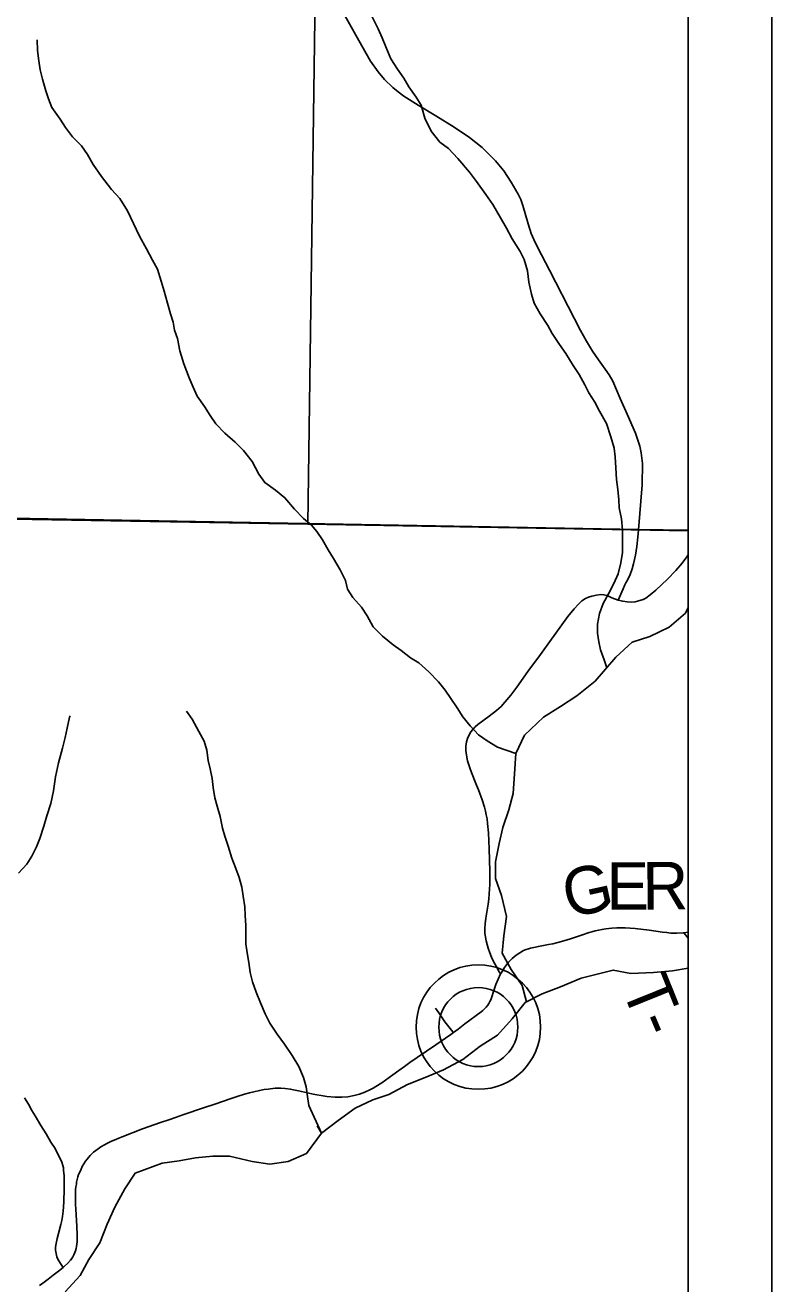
# Model space of a CAD drawing. Extents: x 0 to 34, y -8.9 to 22.
# Drawn here: x 29.724 to 30.617, y 15.866 to 17.37 of the extents above; entities that cross this region are included whole.
import ezdxf

# ---------------------------------------------------------------- set-up
doc = ezdxf.new("R2010")
doc.units = 0
for name, color, linetype in [('GM_X_Corporation', 7, 'Continuous'), ('GM_X_County_Road', 7, 'Continuous'), ('GM_X_County_Road_Text', 7, 'Continuous'), ('GM_X_Minor_River', 7, 'Continuous'), ('GM_X_Township_Road', 7, 'Continuous'), ('GM_X_Township_Road_Text', 7, 'Continuous'), ('GM_X_Unincorporated', 7, 'Continuous'), ('GM_X_Unincorporated_Location', 7, 'Continuous'), ('SH_Data', 7, 'Continuous')]:
    doc.layers.add(name, color=color, linetype=linetype)

msp = doc.modelspace()

# ---------------------------------------------------------------- linework, layer by layer
at = {"layer": 'GM_X_Corporation'}
for points in [[(28.3182, 16.8002), (29.5528, 16.7835), (30.4571, 16.7673), (30.5167, 16.7663), (30.5167, 21.4), (23.7167, 21.4)], [(23.7167, 14.6), (30.5167, 14.6), (30.5167, 16.7663), (30.4571, 16.7673), (29.5528, 16.7835), (28.3182, 16.8002)]]:
    msp.add_lwpolyline(points, dxfattribs=at)
for points in [[(30.5167, 16.7663), (30.5167, 21.4), (28.2203, 21.4), (28.2198, 21.3092), (28.2124, 18.7899), (28.2124, 18.7889), (28.2011, 18.1006), (28.201, 18.0921), (28.1882, 17.3108), (28.1928, 16.8054), (28.3182, 16.8002), (29.5528, 16.7835), (30.4571, 16.7673)], [(30.0751, 17.7225), (30.0622, 16.7735), (29.0733, 16.7902), (29.0677, 17.7366)], [(30.5167, 16.7657), (30.5167, 17.7179), (30.0751, 17.7225), (30.0622, 16.7735)], [(28.1739, 14.6), (30.5167, 14.6), (30.5167, 16.7663), (30.4571, 16.7673), (29.5528, 16.7835), (28.3182, 16.8002), (28.1928, 16.8054), (28.1817, 16.6637), (28.1846, 16.3341), (28.1918, 16.1509), (28.1809, 15.2987)]]:
    msp.add_lwpolyline(points, close=True, dxfattribs=at)
at = {"layer": 'GM_X_County_Road'}
for points in [[(30.4573, 16.7667), (30.4615, 16.8207), (30.4621, 16.8461), (30.4606, 16.8589), (30.4588, 16.8668), (30.4536, 16.8821), (30.4438, 16.9048), (30.4354, 16.9237), (30.4267, 16.9442), (30.4223, 16.9521), (30.4176, 16.9588), (30.4094, 16.97), (30.4025, 16.9801), (30.395, 16.9921), (30.3879, 17.005), (30.3584, 17.0623), (30.3508, 17.077), (30.3414, 17.0954), (30.334, 17.1101), (30.3292, 17.121), (30.3256, 17.1326), (30.3191, 17.1542), (30.3166, 17.1614), (30.3133, 17.1678), (30.3052, 17.1824), (30.2962, 17.1956), (30.2864, 17.2077), (30.2703, 17.2235), (30.2554, 17.2356), (30.237, 17.2478), (30.215, 17.2616), (30.1941, 17.2742), (30.1767, 17.2849), (30.1699, 17.2901), (30.1635, 17.2954), (30.1538, 17.3048), (30.1461, 17.3142), (30.1371, 17.3268), (30.1266, 17.3451), (30.1026, 17.3879)], [(30.433, 16.6827), (30.4334, 16.6836), (30.4373, 16.6926), (30.4388, 16.6963), (30.441, 16.7009), (30.4423, 16.7035), (30.444, 16.7066), (30.4455, 16.7095), (30.4468, 16.712), (30.4482, 16.7156), (30.449, 16.7179), (30.4497, 16.7203), (30.4514, 16.7262), (30.4537, 16.7365), (30.4554, 16.7468), (30.4564, 16.7579), (30.4573, 16.7667)], [(30.433, 16.6827), (30.4384, 16.6813), (30.4438, 16.6805), (30.4493, 16.6804), (30.4535, 16.6808), (30.4588, 16.6821), (30.4628, 16.6835), (30.4659, 16.6852), (30.4714, 16.6891), (30.4781, 16.6946), (30.4921, 16.7077), (30.502, 16.718), (30.5096, 16.7269), (30.5151, 16.7343), (30.5167, 16.7368)], [(30.2925, 16.2361), (30.2908, 16.2385), (30.2875, 16.2444), (30.2836, 16.2517), (30.2817, 16.2561), (30.2797, 16.2611), (30.2778, 16.2668), (30.2764, 16.2713), (30.2753, 16.2756), (30.2744, 16.2798), (30.2737, 16.2852), (30.2736, 16.2903), (30.2739, 16.296), (30.2748, 16.3028), (30.2776, 16.3194), (30.2785, 16.3255), (30.279, 16.3317), (30.2793, 16.3371), (30.2797, 16.3428), (30.2798, 16.3589), (30.279, 16.3855), (30.2781, 16.4048), (30.277, 16.4158), (30.2763, 16.4214), (30.2754, 16.4262), (30.2744, 16.4304), (30.2732, 16.4352), (30.2705, 16.444), (30.2659, 16.4562), (30.2637, 16.4615), (30.2612, 16.4676), (30.2565, 16.4799), (30.2531, 16.4906), (30.2516, 16.4974), (30.2511, 16.503), (30.2511, 16.5081), (30.2518, 16.5132), (30.253, 16.5175), (30.2548, 16.5216), (30.2571, 16.5254), (30.2595, 16.5283), (30.2619, 16.5311), (30.2653, 16.5341), (30.2789, 16.5439), (30.2877, 16.5507), (30.2931, 16.5557), (30.2977, 16.5606), (30.3048, 16.5692), (30.3117, 16.5787), (30.3249, 16.5976), (30.3402, 16.6179), (30.3535, 16.6359), (30.3567, 16.6404), (30.3657, 16.653), (30.373, 16.663), (30.3804, 16.6724), (30.3854, 16.6779), (30.3897, 16.6817), (30.394, 16.6845), (30.3974, 16.6862), (30.4016, 16.6876), (30.4072, 16.6888), (30.4123, 16.6893), (30.4159, 16.6892), (30.4194, 16.6883), (30.4223, 16.6872), (30.4256, 16.6855), (30.433, 16.6827)], [(30.3396, 16.2692), (30.3496, 16.2711), (30.3549, 16.272), (30.3608, 16.2735), (30.3681, 16.2756), (30.376, 16.278), (30.3821, 16.2801), (30.389, 16.2825), (30.3984, 16.2856), (30.4015, 16.2864), (30.4056, 16.2875), (30.4098, 16.2883), (30.4135, 16.2889), (30.4183, 16.2897), (30.4217, 16.2902), (30.4253, 16.2906), (30.4315, 16.291), (30.4366, 16.2912), (30.4415, 16.2911), (30.4534, 16.2903), (30.4701, 16.2883), (30.4861, 16.286), (30.491, 16.2854), (30.4959, 16.2849), (30.5033, 16.2846), (30.5106, 16.285), (30.5115, 16.2852)], [(30.5115, 16.2852), (30.5166, 16.286), (30.5167, 16.286)], [(30.2925, 16.2361), (30.293, 16.2371), (30.297, 16.2435), (30.302, 16.2499), (30.3064, 16.2545), (30.3112, 16.2585), (30.3154, 16.2614), (30.3199, 16.2638), (30.323, 16.2652), (30.3257, 16.2661), (30.3284, 16.2668), (30.3321, 16.2675), (30.3376, 16.2688), (30.3396, 16.2692)], [(30.236, 16.1659), (30.2417, 16.1701), (30.2497, 16.1762), (30.2691, 16.1907), (30.2713, 16.1924), (30.2736, 16.1948), (30.2753, 16.1964), (30.2772, 16.1988), (30.2783, 16.2005), (30.2797, 16.2031), (30.2807, 16.205), (30.2816, 16.2075), (30.2845, 16.2163), (30.2868, 16.2234), (30.2894, 16.2298), (30.2925, 16.2361)], [(29.7695, 15.8851), (29.7709, 15.8862), (29.7754, 15.8902), (29.7786, 15.8939), (29.7802, 15.896), (29.7813, 15.8979), (29.7825, 15.9002), (29.7835, 15.9029), (29.7844, 15.9051), (29.7851, 15.9077), (29.7856, 15.9104), (29.7858, 15.9129), (29.7862, 15.9159), (29.7862, 15.9239), (29.7858, 15.9344), (29.7847, 15.9549), (29.7844, 15.9605), (29.7843, 15.968), (29.7846, 15.978), (29.7849, 15.9814), (29.7854, 15.9849), (29.7856, 15.9871), (29.7862, 15.9903), (29.7871, 15.9935), (29.7881, 15.9961), (29.7894, 15.9992), (29.791, 16.0028), (29.7925, 16.0058), (29.7943, 16.0089), (29.7963, 16.0121), (29.7982, 16.0147), (29.7999, 16.0166), (29.802, 16.019), (29.8038, 16.0208), (29.8061, 16.0229), (29.8086, 16.025), (29.8116, 16.0271), (29.8148, 16.0292), (29.819, 16.0318), (29.8228, 16.0338), (29.8274, 16.036), (29.8325, 16.0382), (29.8361, 16.0398), (29.84, 16.0414), (29.8645, 16.0507), (29.8861, 16.0583), (29.8958, 16.0617), (29.9038, 16.0645), (29.9125, 16.0676), (29.9372, 16.076), (29.9508, 16.0804), (29.9614, 16.084), (29.9694, 16.0868), (29.979, 16.0901), (29.9862, 16.0922), (29.9922, 16.0938), (29.9977, 16.0952), (30.0044, 16.0965), (30.01, 16.0977), (30.0148, 16.0984), (30.0229, 16.0993), (30.0262, 16.0994), (30.0299, 16.0993), (30.0349, 16.0991), (30.0411, 16.0983), (30.0509, 16.0964), (30.0618, 16.0939), (30.0684, 16.0925), (30.073, 16.0916), (30.0782, 16.0907), (30.0849, 16.0897), (30.0947, 16.0887), (30.1027, 16.0886), (30.11, 16.0893), (30.1173, 16.0907), (30.1238, 16.0925), (30.1301, 16.0948), (30.1368, 16.0979), (30.1402, 16.0996), (30.1434, 16.1014), (30.1506, 16.106), (30.1637, 16.1154), (30.1707, 16.1205), (30.1775, 16.1255), (30.1841, 16.1301), (30.1929, 16.1363), (30.215, 16.1513), (30.2329, 16.1636), (30.236, 16.1659)], [(29.7414, 15.8637), (29.7454, 15.8664), (29.7519, 15.8714), (29.7577, 15.8758), (29.7641, 15.8808), (29.7695, 15.8851)]]:
    msp.add_lwpolyline(points, dxfattribs=at)
at = {"layer": 'GM_X_Minor_River'}
for points in [[(30.4382, 16.7663), (30.4368, 16.7797), (30.4344, 16.793), (30.4339, 16.8025), (30.4326, 16.815), (30.4309, 16.8267), (30.4303, 16.8408), (30.4294, 16.8541), (30.4281, 16.8643), (30.4242, 16.8779), (30.419, 16.8938), (30.4105, 16.9085), (30.405, 16.9194), (30.398, 16.9304), (30.393, 16.9402), (30.3864, 16.9522), (30.3794, 16.9632), (30.3705, 16.9775), (30.3628, 16.9884), (30.3542, 17.0012), (30.3488, 17.011), (30.3399, 17.0249), (30.3325, 17.0378), (30.3293, 17.0483), (30.3261, 17.0627), (30.3248, 17.0764), (30.3208, 17.0896), (30.3158, 17.0994), (30.3065, 17.1145), (30.2995, 17.1273), (30.2921, 17.1405), (30.2832, 17.1556), (30.275, 17.1676), (30.2635, 17.1831), (30.2553, 17.194), (30.2415, 17.2105), (30.2303, 17.2225), (30.22, 17.23), (30.2095, 17.2431), (30.2018, 17.2586), (30.1974, 17.2741), (30.1916, 17.2839), (30.1827, 17.2963), (30.1768, 17.3065), (30.1691, 17.3174), (30.1614, 17.3298), (30.1555, 17.3438), (30.1508, 17.3548), (30.1461, 17.3653), (30.1383, 17.3812)], [(30.0664, 16.7722), (30.057, 16.7802), (30.0463, 16.7914), (30.0347, 16.805), (30.0236, 16.8143), (30.0106, 16.8232), (30.0036, 16.8334), (29.9954, 16.8485), (29.985, 16.8617), (29.9754, 16.8714), (29.9627, 16.8823), (29.952, 16.8935), (29.9454, 16.9033), (29.9384, 16.9142), (29.9299, 16.9266), (29.9252, 16.9372), (29.9201, 16.9482), (29.9138, 16.9652), (29.9091, 16.9807), (29.9062, 16.9954), (29.9027, 17.0053), (29.901, 17.0151), (29.8979, 17.025), (29.8943, 17.0378), (29.8903, 17.0518), (29.8867, 17.0639), (29.8824, 17.0783), (29.8765, 17.0889), (29.8692, 17.1024), (29.861, 17.1175), (29.8536, 17.133), (29.8466, 17.1481), (29.8373, 17.1628), (29.8276, 17.1733), (29.8153, 17.1891), (29.8056, 17.2034), (29.7986, 17.2154), (29.7917, 17.2256), (29.7809, 17.2365), (29.7724, 17.2474), (29.7662, 17.2576), (29.7562, 17.2715), (29.7522, 17.2817), (29.7491, 17.2915), (29.7451, 17.3055), (29.7423, 17.3165), (29.7406, 17.3271), (29.7389, 17.3396), (29.7384, 17.3525)], [(30.3107, 16.4994), (30.2888, 16.507), (30.2766, 16.5144), (30.2662, 16.5217), (30.256, 16.5324), (30.2474, 16.5434), (30.2406, 16.554), (30.2331, 16.5653), (30.2263, 16.5751), (30.2183, 16.585), (30.2067, 16.5969), (30.1949, 16.6077), (30.1849, 16.6138), (30.1735, 16.6227), (30.1639, 16.6292), (30.1514, 16.6396), (30.1401, 16.6508), (30.133, 16.664), (30.1262, 16.6742), (30.116, 16.6857), (30.1096, 16.6958), (30.107, 16.7062), (30.1007, 16.719), (30.0929, 16.7323), (30.0865, 16.7429), (30.0798, 16.7546), (30.073, 16.7647), (30.0664, 16.7722)], [(30.4196, 16.6018), (30.4162, 16.6114), (30.4117, 16.6234), (30.4099, 16.633), (30.4084, 16.6433), (30.4085, 16.654), (30.4105, 16.6668), (30.4149, 16.6788), (30.4214, 16.6903), (30.428, 16.7026), (30.4331, 16.7142), (30.4363, 16.7274), (30.438, 16.7395), (30.4382, 16.7663)], [(30.3235, 16.2026), (30.3182, 16.2223), (30.305, 16.2413), (30.2944, 16.2607), (30.2963, 16.2815), (30.2997, 16.3047), (30.2936, 16.3297), (30.2864, 16.3502), (30.2864, 16.37), (30.2906, 16.392), (30.2951, 16.411), (30.3023, 16.4322), (30.3076, 16.4516), (30.3091, 16.4751), (30.3107, 16.4994), (30.3212, 16.5214), (30.3439, 16.5427), (30.364, 16.5556), (30.3837, 16.5685), (30.4056, 16.586), (30.4302, 16.6144), (30.4498, 16.6323), (30.471, 16.6391), (30.4941, 16.6505), (30.5134, 16.6672), (30.5167, 16.6741)], [(30.0733, 16.0544), (30.0784, 16.0458), (30.0633, 16.0788), (30.0618, 16.0895), (30.06, 16.101), (30.0571, 16.1122), (30.0512, 16.1254), (30.0434, 16.1387), (30.0344, 16.152), (30.0254, 16.1642), (30.0168, 16.1771), (30.0112, 16.1884), (30.0057, 16.2015), (30.0005, 16.2143), (29.9961, 16.2267), (29.9932, 16.2378), (29.9914, 16.2497), (29.9896, 16.2612), (29.9881, 16.2719), (29.9879, 16.294), (29.9873, 16.3058), (29.9866, 16.3161), (29.9849, 16.3291), (29.9834, 16.3398), (29.9801, 16.3514), (29.976, 16.3619), (29.9712, 16.3742), (29.9668, 16.3885), (29.9628, 16.4005), (29.9601, 16.4101), (29.9573, 16.4243), (29.9537, 16.4366), (29.951, 16.4463), (29.9489, 16.4589), (29.9478, 16.4696), (29.9453, 16.4811), (29.943, 16.4911), (29.9413, 16.5034), (29.9383, 16.5141), (29.9319, 16.5258), (29.9238, 16.5406), (29.917, 16.5501)], [(29.7162, 16.3563), (29.7262, 16.3673), (29.7323, 16.3769), (29.7377, 16.3877), (29.7416, 16.3978), (29.7464, 16.4125), (29.7503, 16.4249), (29.7548, 16.4395), (29.7581, 16.455), (29.7603, 16.4716), (29.7641, 16.4882), (29.769, 16.5059), (29.7722, 16.5186), (29.7746, 16.5296), (29.7774, 16.5428), (29.7779, 16.5443)], [(29.772, 15.856), (29.7898, 15.8754), (29.8004, 15.8948), (29.8133, 15.9145), (29.8224, 15.9369), (29.8314, 15.9574), (29.8432, 15.979), (29.8556, 15.998), (29.8878, 16.0098), (29.9082, 16.0128), (29.9279, 16.0162), (29.9487, 16.0181), (29.9683, 16.0181), (29.9956, 16.0117), (30.0168, 16.0086), (30.0387, 16.0117), (30.0603, 16.0215), (30.0784, 16.0458), (30.0985, 16.061), (30.1185, 16.0754), (30.1397, 16.0857), (30.159, 16.0918), (30.1813, 16.1039), (30.2025, 16.1122), (30.2244, 16.1214), (30.2475, 16.1339), (30.2679, 16.1498), (30.2887, 16.1627), (30.3065, 16.1825), (30.322, 16.2018), (30.342, 16.2124), (30.364, 16.2204), (30.3889, 16.231), (30.4272, 16.2405), (30.4483, 16.2364), (30.4752, 16.2379), (30.4979, 16.2398), (30.5167, 16.2428)]]:
    msp.add_lwpolyline(points, dxfattribs=at)
at = {"layer": 'GM_X_Township_Road'}
for points in [[(30.5115, 16.2852), (30.5135, 16.2827), (30.5167, 16.2786)], [(30.236, 16.1659), (30.2354, 16.1666), (30.226, 16.1789), (30.2228, 16.1834), (30.2186, 16.1895), (30.2147, 16.1951)], [(29.7695, 15.8851), (29.768, 15.8875), (29.7637, 15.8942), (29.762, 15.8981), (29.7611, 15.9017), (29.7605, 15.9059), (29.7605, 15.9096), (29.7611, 15.9138), (29.7625, 15.9199), (29.7642, 15.9258), (29.7669, 15.9366), (29.7681, 15.9415), (29.7688, 15.9463), (29.7696, 15.9525), (29.7701, 15.9576), (29.7704, 15.9636), (29.7707, 15.9791), (29.7707, 15.9883), (29.7707, 15.9946), (29.7702, 16.0014), (29.7699, 16.0043), (29.7692, 16.0069), (29.7679, 16.011), (29.7659, 16.0153), (29.7645, 16.0183), (29.7599, 16.0272), (29.7551, 16.0351), (29.7492, 16.0447), (29.743, 16.0547), (29.7362, 16.0663), (29.7324, 16.0729), (29.7282, 16.0802), (29.7236, 16.088)]]:
    msp.add_lwpolyline(points, dxfattribs=at)
at = {"layer": 'GM_X_Unincorporated'}
for radius in [0.0744, 0.0472]:
    msp.add_circle((30.2659, 16.1725), radius, dxfattribs=at)
at = {"layer": 'GM_X_Unincorporated_Location'}
msp.add_line((30.2659, 16.1725), (30.2659, 16.1725), dxfattribs=at)
at = {"layer": 'SH_Data'}
for points in [[(23.6167, 21.5), (30.6167, 21.5), (30.6167, 14.5), (23.6167, 14.5)], [(23.7167, 21.4), (30.5167, 21.4), (30.5167, 14.6), (23.7167, 14.6)]]:
    msp.add_lwpolyline(points, close=True, dxfattribs=at)

# ---------------------------------------------------------------- texts
at = {"layer": 'GM_X_County_Road_Text'}
for s, rotation, p in [('G', 12.3388, (30.3735, 16.3024)), ('E', 0.06, (30.4191, 16.3127)), ('R', 0.5745, (30.4622, 16.3128))]:
    msp.add_text(s, height=0.0568, rotation=rotation, dxfattribs=at).set_placement(p)
at = {"layer": 'GM_X_Township_Road_Text'}
for s, rotation, p in [('T', 291.9705, (30.4363, 16.22)), ('-', 292.9483, (30.4526, 16.1797))]:
    msp.add_text(s, height=0.0568, rotation=rotation, dxfattribs=at).set_placement(p)

doc.saveas('drawing.dxf')
